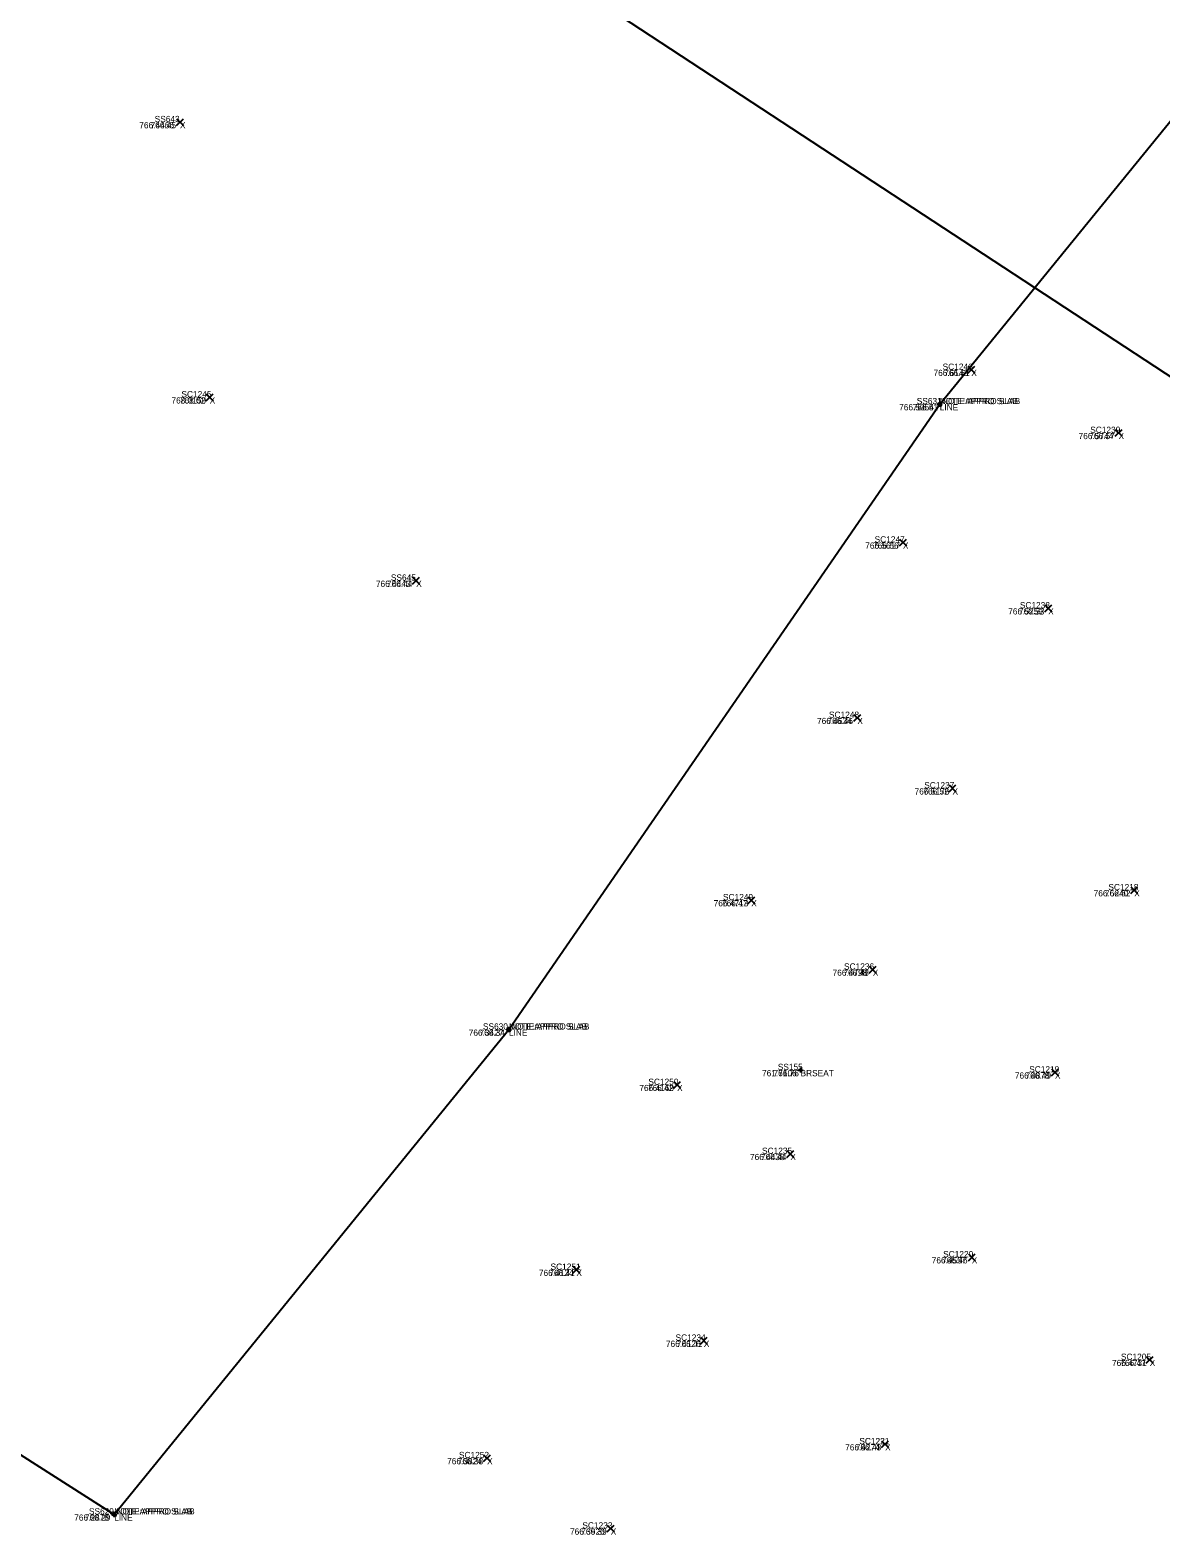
# Model space of a CAD drawing. Extents: x 1845019 to 1877956, y 680444 to 701081.
# Drawn here: x 1857549.07 to 1857559.96, y 694336.67 to 694351.2 of the extents above; entities that cross this region are included whole.
import ezdxf

# ---------------------------------------------------------------- set-up
doc = ezdxf.new("R2010")
doc.units = 0
for name, color, linetype in [('BR_X_SV_Beam_Seat', 7, 'Continuous'), ('Default', 7, 'Continuous'), ('SV_X_CL_Survey_20', 7, 'Continuous'), ('SV_X_Random_Point', 7, 'Continuous'), ('SV_X_Shot_Marker', 7, 'Continuous'), ('SV_X_Text_Comment', 7, 'Continuous'), ('SV_X_Text_Description', 7, 'Continuous'), ('SV_X_Text_Elevation', 7, 'Continuous'), ('SV_X_Text_Name', 7, 'Continuous')]:
    doc.layers.add(name, color=color, linetype=linetype)

msp = doc.modelspace()

# ---------------------------------------------------------------- linework, layer by layer
at = {"layer": 'BR_X_SV_Beam_Seat'}
for p, q in [((1857556.463, 694341.183), (1857556.513, 694341.183)), ((1857556.463, 694341.183), (1857556.513, 694341.183)), ((1857556.488, 694341.208), (1857556.488, 694341.158)), ((1857556.488, 694341.208), (1857556.488, 694341.158)), ((1857556.488, 694341.183), (1857556.488, 694341.183)), ((1857556.488, 694341.183), (1857556.488, 694341.183))]:
    msp.add_line(p, q, dxfattribs=at)
at = {"layer": 'Default'}
msp.add_lwpolyline([(1857529.179, 694350.113), (1857549.875, 694336.9), (1857553.678, 694341.573), (1857557.829, 694347.6), (1857560.398, 694350.754), (1857568.363, 694361.498), (1857547.247, 694374.307), (1857542.393, 694367.435), (1857538.138, 694361.818), (1857529.244, 694350.474)], dxfattribs=at)
msp.add_lwpolyline([(1857529.179, 694350.113), (1857549.875, 694336.9), (1857553.678, 694341.573), (1857557.829, 694347.6), (1857560.398, 694350.754), (1857568.363, 694361.498), (1857547.247, 694374.307), (1857542.393, 694367.435), (1857538.138, 694361.818), (1857529.244, 694350.474)], dxfattribs=at)
at = {"layer": 'SV_X_CL_Survey_20'}
msp.add_line((1856038.267, 695346.314), (1858797.327, 693536.085), dxfattribs=at)
at = {"layer": 'SV_X_Random_Point'}
for p, q in [((1857550.475, 694350.284), (1857550.542, 694350.351)), ((1857550.475, 694350.351), (1857550.542, 694350.284)), ((1857550.475, 694350.284), (1857550.542, 694350.351)), ((1857550.475, 694350.351), (1857550.542, 694350.284)), ((1857558.099, 694347.898), (1857558.166, 694347.965)), ((1857558.099, 694347.965), (1857558.166, 694347.898)), ((1857558.099, 694347.898), (1857558.166, 694347.965)), ((1857558.099, 694347.965), (1857558.166, 694347.898)), ((1857550.761, 694347.632), (1857550.828, 694347.699)), ((1857550.761, 694347.699), (1857550.828, 694347.632)), ((1857550.761, 694347.632), (1857550.828, 694347.699)), ((1857550.761, 694347.699), (1857550.828, 694347.632)), ((1857559.519, 694347.29), (1857559.586, 694347.357)), ((1857559.519, 694347.357), (1857559.586, 694347.29)), ((1857559.519, 694347.29), (1857559.586, 694347.357)), ((1857559.519, 694347.357), (1857559.586, 694347.29)), ((1857557.441, 694346.234), (1857557.508, 694346.3)), ((1857557.441, 694346.3), (1857557.508, 694346.234)), ((1857557.441, 694346.234), (1857557.508, 694346.3)), ((1857557.441, 694346.3), (1857557.508, 694346.234)), ((1857552.751, 694345.865), (1857552.818, 694345.932)), ((1857552.751, 694345.932), (1857552.818, 694345.865)), ((1857552.751, 694345.865), (1857552.818, 694345.932)), ((1857552.751, 694345.932), (1857552.818, 694345.865)), ((1857558.841, 694345.599), (1857558.908, 694345.666)), ((1857558.841, 694345.666), (1857558.908, 694345.599)), ((1857558.841, 694345.599), (1857558.908, 694345.666)), ((1857558.841, 694345.666), (1857558.908, 694345.599)), ((1857557.001, 694344.544), (1857557.068, 694344.61)), ((1857557.001, 694344.61), (1857557.068, 694344.544)), ((1857557.001, 694344.544), (1857557.068, 694344.61)), ((1857557.001, 694344.61), (1857557.068, 694344.544)), ((1857557.919, 694343.865), (1857557.985, 694343.932)), ((1857557.919, 694343.932), (1857557.985, 694343.865)), ((1857557.919, 694343.865), (1857557.985, 694343.932)), ((1857557.919, 694343.932), (1857557.985, 694343.865)), ((1857555.98, 694342.786), (1857556.047, 694342.853)), ((1857555.98, 694342.853), (1857556.047, 694342.786)), ((1857555.98, 694342.786), (1857556.047, 694342.853)), ((1857555.98, 694342.853), (1857556.047, 694342.786)), ((1857559.67, 694342.883), (1857559.736, 694342.949)), ((1857559.67, 694342.949), (1857559.736, 694342.883)), ((1857559.67, 694342.883), (1857559.736, 694342.949)), ((1857559.67, 694342.949), (1857559.736, 694342.883)), ((1857557.15, 694342.117), (1857557.217, 694342.184)), ((1857557.15, 694342.184), (1857557.217, 694342.117)), ((1857557.15, 694342.117), (1857557.217, 694342.184)), ((1857557.15, 694342.184), (1857557.217, 694342.117)), ((1857558.906, 694341.127), (1857558.973, 694341.193)), ((1857558.906, 694341.193), (1857558.973, 694341.127)), ((1857558.906, 694341.127), (1857558.973, 694341.193)), ((1857558.906, 694341.193), (1857558.973, 694341.127)), ((1857555.266, 694341.007), (1857555.333, 694341.073)), ((1857555.266, 694341.073), (1857555.333, 694341.007)), ((1857555.266, 694341.007), (1857555.333, 694341.073)), ((1857555.266, 694341.073), (1857555.333, 694341.007)), ((1857556.356, 694340.341), (1857556.423, 694340.408)), ((1857556.356, 694340.408), (1857556.423, 694340.341)), ((1857556.356, 694340.341), (1857556.423, 694340.408)), ((1857556.356, 694340.408), (1857556.423, 694340.341)), ((1857558.105, 694339.345), (1857558.172, 694339.412)), ((1857558.105, 694339.412), (1857558.172, 694339.345)), ((1857558.105, 694339.345), (1857558.172, 694339.412)), ((1857558.105, 694339.412), (1857558.172, 694339.345)), ((1857554.295, 694339.225), (1857554.361, 694339.292)), ((1857554.295, 694339.292), (1857554.361, 694339.225)), ((1857554.295, 694339.225), (1857554.361, 694339.292)), ((1857554.295, 694339.292), (1857554.361, 694339.225)), ((1857555.523, 694338.542), (1857555.59, 694338.608)), ((1857555.523, 694338.608), (1857555.59, 694338.542)), ((1857555.523, 694338.542), (1857555.59, 694338.608)), ((1857555.523, 694338.608), (1857555.59, 694338.542)), ((1857559.819, 694338.357), (1857559.885, 694338.423)), ((1857559.819, 694338.423), (1857559.885, 694338.357)), ((1857559.819, 694338.357), (1857559.885, 694338.423)), ((1857559.819, 694338.423), (1857559.885, 694338.357)), ((1857557.269, 694337.544), (1857557.336, 694337.61)), ((1857557.269, 694337.61), (1857557.336, 694337.544)), ((1857557.269, 694337.544), (1857557.336, 694337.61)), ((1857557.269, 694337.61), (1857557.336, 694337.544)), ((1857553.435, 694337.409), (1857553.501, 694337.476)), ((1857553.435, 694337.476), (1857553.501, 694337.409)), ((1857553.435, 694337.409), (1857553.501, 694337.476)), ((1857553.435, 694337.476), (1857553.501, 694337.409)), ((1857554.625, 694336.731), (1857554.692, 694336.798)), ((1857554.625, 694336.798), (1857554.692, 694336.731)), ((1857554.625, 694336.731), (1857554.692, 694336.798)), ((1857554.625, 694336.798), (1857554.692, 694336.731))]:
    msp.add_line(p, q, dxfattribs=at)
at = {"layer": 'SV_X_Shot_Marker'}
for p, q in [((1857557.804, 694347.6), (1857557.854, 694347.6)), ((1857557.808, 694347.614), (1857557.849, 694347.586)), ((1857557.815, 694347.58), (1857557.843, 694347.621)), ((1857557.829, 694347.625), (1857557.829, 694347.575)), ((1857557.829, 694347.6), (1857557.829, 694347.6)), ((1857557.829, 694347.6), (1857557.829, 694347.6)), ((1857553.653, 694341.573), (1857553.703, 694341.573)), ((1857553.658, 694341.589), (1857553.697, 694341.558)), ((1857553.662, 694341.554), (1857553.694, 694341.593)), ((1857553.678, 694341.598), (1857553.678, 694341.548)), ((1857553.678, 694341.573), (1857553.678, 694341.573)), ((1857553.678, 694341.573), (1857553.678, 694341.573)), ((1857549.85, 694336.9), (1857549.9, 694336.9)), ((1857549.854, 694336.914), (1857549.896, 694336.887)), ((1857549.888, 694336.921), (1857549.861, 694336.879)), ((1857549.875, 694336.925), (1857549.875, 694336.875)), ((1857549.875, 694336.9), (1857549.875, 694336.9)), ((1857549.875, 694336.9), (1857549.875, 694336.9))]:
    msp.add_line(p, q, dxfattribs=at)

# ---------------------------------------------------------------- texts
at = {"layer": 'BR_X_SV_Beam_Seat'}
for s, p in [('SS155', (1857556.269, 694341.183)), ('SS155', (1857556.269, 694341.183)), ('761.7606', (1857556.117, 694341.123)), ('761.76', (1857556.227, 694341.123)), ('BRSEAT', (1857556.488, 694341.123))]:
    msp.add_text(s, height=0.06, dxfattribs=at).set_placement(p)
at = {"layer": 'SV_X_Text_Comment'}
for s, p in [('X', (1857550.509, 694350.258)), ('X', (1857558.133, 694347.871)), ('X', (1857550.795, 694347.606)), ('LINE', (1857557.829, 694347.54)), ('X', (1857559.552, 694347.263)), ('X', (1857557.474, 694346.207)), ('X', (1857552.785, 694345.839)), ('X', (1857558.874, 694345.573)), ('X', (1857557.035, 694344.517)), ('X', (1857557.952, 694343.838)), ('X', (1857559.703, 694342.856)), ('X', (1857556.013, 694342.76)), ('X', (1857557.184, 694342.091)), ('LINE', (1857553.678, 694341.513)), ('X', (1857558.939, 694341.1)), ('X', (1857555.299, 694340.98)), ('X', (1857556.39, 694340.315)), ('X', (1857558.138, 694339.319)), ('X', (1857554.328, 694339.198)), ('X', (1857555.556, 694338.515)), ('X', (1857559.852, 694338.33)), ('X', (1857557.303, 694337.517)), ('X', (1857553.468, 694337.383)), ('LINE', (1857549.875, 694336.84)), ('X', (1857554.659, 694336.705))]:
    msp.add_text(s, height=0.06, dxfattribs=at).set_placement(p)
at = {"layer": 'SV_X_Text_Description'}
for s, p in [('NOTE:APPRO SLAB', (1857557.829, 694347.6)), (' NOTE:APPRO SLAB', (1857557.829, 694347.6)), ('NOTE:APPRO SLAB', (1857553.678, 694341.573)), (' NOTE:APPRO SLAB', (1857553.678, 694341.573)), ('NOTE:APPRO SLAB', (1857549.875, 694336.9)), (' NOTE:APPRO SLAB', (1857549.875, 694336.9))]:
    msp.add_text(s, height=0.06, dxfattribs=at).set_placement(p)
at = {"layer": 'SV_X_Text_Elevation'}
for s, p in [('766.4466', (1857550.117, 694350.258)), ('766.45', (1857550.226, 694350.258)), ('766.6143', (1857557.769, 694347.871)), ('766.61', (1857557.872, 694347.871)), ('768.0159', (1857550.427, 694347.606)), ('768.02', (1857550.508, 694347.606)), ('766.5054', (1857557.438, 694347.54)), ('766.51', (1857557.569, 694347.54)), ('766.5744', (1857559.167, 694347.263)), ('766.57', (1857559.27, 694347.263)), ('766.5617', (1857557.111, 694346.207)), ('766.56', (1857557.188, 694346.207)), ('766.4443', (1857552.397, 694345.839)), ('766.44', (1857552.503, 694345.839)), ('766.5259', (1857558.489, 694345.573)), ('766.53', (1857558.592, 694345.573)), ('766.4634', (1857556.647, 694344.517)), ('766.46', (1857556.748, 694344.517)), ('766.5176', (1857557.587, 694343.838)), ('766.52', (1857557.671, 694343.838)), ('766.5240', (1857559.312, 694342.856)), ('766.52', (1857559.421, 694342.856)), ('766.4713', (1857555.651, 694342.76)), ('766.47', (1857555.731, 694342.76)), ('766.4798', (1857556.797, 694342.091)), ('766.48', (1857556.901, 694342.091)), ('766.3427', (1857553.291, 694341.513)), ('766.34', (1857553.395, 694341.513)), ('766.4878', (1857558.553, 694341.1)), ('766.49', (1857558.656, 694341.1)), ('766.4169', (1857554.935, 694340.98)), ('766.42', (1857555.017, 694340.98)), ('766.4438', (1857556.001, 694340.315)), ('766.44', (1857556.107, 694340.315)), ('766.4557', (1857557.752, 694339.319)), ('766.46', (1857557.852, 694339.319)), ('766.4124', (1857553.967, 694339.198)), ('766.41', (1857554.068, 694339.198)), ('766.4126', (1857555.191, 694338.515)), ('766.41', (1857555.296, 694338.515)), ('766.4731', (1857559.489, 694338.33)), ('766.47', (1857559.569, 694338.33)), ('766.4274', (1857556.918, 694337.517)), ('766.43', (1857557.02, 694337.517)), ('766.3824', (1857553.083, 694337.383)), ('766.38', (1857553.185, 694337.383)), ('766.2878', (1857549.49, 694336.84)), ('766.29', (1857549.593, 694336.84)), ('766.3920', (1857554.267, 694336.705)), ('766.39', (1857554.375, 694336.705))]:
    msp.add_text(s, height=0.06, dxfattribs=at).set_placement(p)
at = {"layer": 'SV_X_Text_Name'}
for s, p in [('SS643', (1857550.265, 694350.318)), ('SS643', (1857550.265, 694350.318)), ('SC1246', (1857557.857, 694347.931)), ('SC1246', (1857557.857, 694347.931)), ('SC1245', (1857550.523, 694347.666)), ('SC1245', (1857550.523, 694347.666)), ('SS631', (1857557.607, 694347.6)), ('SS631', (1857557.608, 694347.6)), ('SC1239', (1857559.279, 694347.323)), ('SC1239', (1857559.279, 694347.323)), ('SC1247', (1857557.202, 694346.267)), ('SC1247', (1857557.202, 694346.267)), ('SS645', (1857552.541, 694345.899)), ('SS645', (1857552.541, 694345.899)), ('SC1238', (1857558.601, 694345.633)), ('SC1238', (1857558.601, 694345.633)), ('SC1248', (1857556.762, 694344.577)), ('SC1248', (1857556.762, 694344.577)), ('SC1237', (1857557.68, 694343.898)), ('SC1237', (1857557.68, 694343.898)), ('SC1249', (1857555.741, 694342.82)), ('SC1249', (1857555.741, 694342.82)), ('SC1218', (1857559.454, 694342.916)), ('SC1218', (1857559.454, 694342.916)), ('SC1236', (1857556.907, 694342.151)), ('SC1236', (1857556.907, 694342.151)), ('SS630', (1857553.428, 694341.573)), ('SS630', (1857553.428, 694341.573)), ('SC1250', (1857555.022, 694341.04)), ('SC1250', (1857555.022, 694341.04)), ('SC1219', (1857558.691, 694341.16)), ('SC1219', (1857558.691, 694341.16)), ('SC1235', (1857556.117, 694340.375)), ('SC1235', (1857556.117, 694340.375)), ('SC1220', (1857557.862, 694339.379)), ('SC1220', (1857557.862, 694339.379)), ('SC1251', (1857554.079, 694339.258)), ('SC1251', (1857554.08, 694339.258)), ('SC1234', (1857555.284, 694338.575)), ('SC1234', (1857555.284, 694338.575)), ('SC1205', (1857559.575, 694338.39)), ('SC1205', (1857559.575, 694338.39)), ('SC1221', (1857557.054, 694337.577)), ('SC1221', (1857557.055, 694337.577)), ('SC1252', (1857553.197, 694337.443)), ('SC1252', (1857553.197, 694337.443)), ('SS629', (1857549.632, 694336.9)), ('SS629', (1857549.632, 694336.9)), ('SC1233', (1857554.386, 694336.765)), ('SC1233', (1857554.386, 694336.765))]:
    msp.add_text(s, height=0.06, dxfattribs=at).set_placement(p)

doc.saveas('drawing.dxf')
